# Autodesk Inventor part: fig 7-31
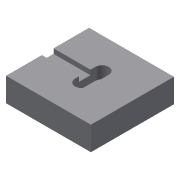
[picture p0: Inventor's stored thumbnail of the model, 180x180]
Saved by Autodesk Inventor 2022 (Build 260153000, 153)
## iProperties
Created: 2004-05
Part Number: fig 7-31
Document SubType Name: Modeling
Designer: CADCIM Technologies
Manufacturer: Standard
Standards Organization: Custom
Density: 1 g/cm^3
Material: Generic
Appearance: Default
Author: CADCIM Technologies
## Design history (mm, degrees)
sketch "Sketch1"
  geometry: L1 (-30.233, -25.517)-(22.302, -25.517); L2 (22.302, -25.517)-(22.302, 25.904); L3 (22.302, 25.904)-(-30.233, 25.904); L4 (-30.233, 25.904)-(-30.233, -25.517)
  constraints: 8 end point, 2 parallel, 1 horizontal, 1 perpendicular
extrude "Extrusion1" new body sketch "Sketch1" distance "d0" = 14.75; taper "d1" = 0 deg
sketch "Sketch2"
  geometry: L1 (1.047, -5.75)-(1.047, 6.846); L2 (-7.35, 6.845)-(-7.35, -5.75); A1 r 4.198 centre (-3.152, 6.846) between (1.047, 6.846) and (-7.35, 6.845); A2 r 4.198 centre (-3.152, -5.75) between (-7.35, -5.75) and (1.047, -5.75)
  constraints: 4 end point, 4 point on circle, 4 tangent, 2 centre point, 1 parallel
extrude "Extrusion2" cut sketch "Sketch2" distance "d2" = 7.5; taper "d3" = 0 deg
sketch "Sketch3"
  geometry: L1 (-7.5, 0)-(-7.5, 12.595) reference; L2 (-7.5, 0)-(0, 0) reference; L3 (-7.5, 2.416)-(-4.537, 2.416); L4 (-4.537, 2.416)-(-4.537, 9.616); L5 (-4.537, 9.616)-(-7.5, 9.616)
  constraints: 6 end point, 2 perpendicular, 2 point on line, 1 parallel
extrude "Extrusion3" cut sketch "Sketch3" extent not by distance; stored distance "d4" = 6.75; taper "d5" = 0 deg
body "Solid1"
